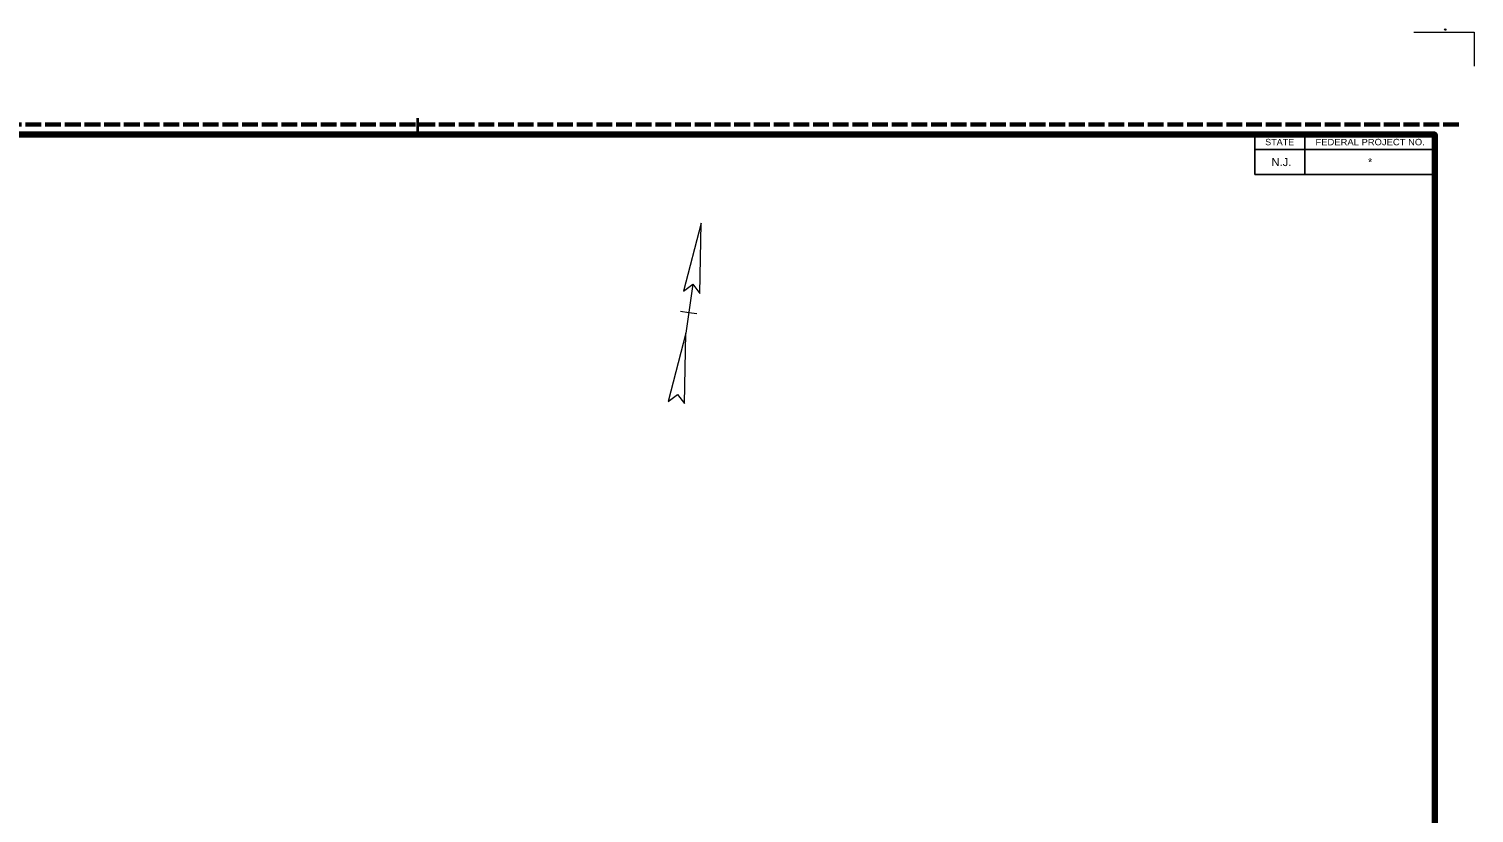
# Model space of a CAD drawing. Extents: x 168423 to 169398, y 223542 to 223937.
# Drawn here: x 169232.6 to 169397.8, y 223631.6 to 223721.2 of the extents above; entities that cross this region are included whole.
import ezdxf
from ezdxf.enums import TextEntityAlignment as Align

# ---------------------------------------------------------------- set-up
doc = ezdxf.new("R2010")
doc.units = 0
doc.header["$LTSCALE"] = 0.3
doc.header["$PDMODE"] = 32
doc.header["$PDSIZE"] = 0.15
doc.linetypes.add('LONG_DASHED', pattern=[7.5, 6, -1.5])
doc.layers.add('1', color=7, linetype='Continuous', lineweight=13)

msp = doc.modelspace()

# ---------------------------------------------------------------- linework, layer by layer
at = {"layer": '1', "lineweight": 35}
msp.add_line((169277.0594, 223711.0185), (169277.0594, 223709.1285), dxfattribs=at)
at = {"layer": '1', "linetype": 'LONG_DASHED', "lineweight": 60}
msp.add_line((169396.0594, 223710.2685), (169127.8354, 223710.2685), dxfattribs=at)
at = {"layer": '1', "lineweight": 25}
for p, q in [((169372.7354, 223709.1285), (169372.7354, 223704.5565)), ((169378.4504, 223709.1285), (169378.4504, 223704.5565)), ((169393.3094, 223707.414), (169372.7354, 223707.414)), ((169393.3094, 223704.5565), (169372.7354, 223704.5565))]:
    msp.add_line(p, q, dxfattribs=at)
at = {"layer": '1'}
for p, q in [((169308.5067, 223692.0172), (169307.7335, 223686.4228)), ((169308.0564, 223688.759), (169307.1255, 223688.8877)), ((169308.9873, 223688.6303), (169308.0564, 223688.759))]:
    msp.add_line(p, q, dxfattribs=at)
msp.add_lwpolyline([(169390.9094, 223720.8285), (169397.8094, 223720.8285), (169397.8094, 223716.9285)], dxfattribs=at)
at = {"layer": '1', "lineweight": 158}
msp.add_lwpolyline([(169393.3094, 223547.1285), (169393.3094, 223709.1285), (169160.8094, 223709.1285), (169160.8094, 223547.1285)], close=True, dxfattribs=at)
at = {"layer": '1'}
for points in [[(169307.4471, 223691.2149), (169308.5067, 223692.0172), (169309.309, 223690.9576), (169309.473, 223699.008)], [(169305.7076, 223678.6298), (169306.7672, 223679.432), (169307.5695, 223678.3724), (169307.7335, 223686.4228)]]:
    msp.add_lwpolyline(points, close=True, dxfattribs=at)
msp.add_point((169394.5094, 223721.1285), dxfattribs=at)

# ---------------------------------------------------------------- texts
for s, height, width, p in [('STATE', 0.7315, 1.05, (169375.5929, 223707.9055)), ('FEDERAL PROJECT NO.', 0.7315, 1.1, (169385.9289, 223707.9055)), ('N.J.', 0.9144, 1.05, (169375.7909, 223705.528))]:
    msp.add_text(s, height=height, dxfattribs=dict(at, width=width)).set_placement(p, align=Align.CENTER)
msp.add_text('*', height=0.9144, dxfattribs=at).set_placement((169385.9289, 223705.5195), align=Align.CENTER)

doc.saveas('drawing.dxf')
